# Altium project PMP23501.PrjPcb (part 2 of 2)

## Sheet DCDC_B.SchDoc: LM72880-Q1 EVM Schematic
size 431 x 279 mm; Date: Not shown in title block; ApprovedBy: Not shown in title block; CheckedBy: Not shown in title block; Author: Not shown in title block; CompanyName: Not shown in title block; DrawnBy: K Nielson; Engineer: E Lee; Organization: Not shown in title block; Address1: Not shown in title block; Address2: Not shown in title block; Address3: Not shown in title block; Address4: Not shown in title block; DocumentNumber: 5; Revision: Use project parameter SCH_Rev; SheetNumber: 5; SheetTotal: 7; PageSetup: Record=PageOptions¦CenterHorizontal=True¦CenterVertical=True¦PrintScale=1.00¦XCorrection=1.00¦YCorrection=1.00¦PrintKind=0¦BorderSize=5000000¦LeftOffset=0¦BottomOffset=0¦Orientation=2¦PaperLength=1000¦PaperWidth=1000¦Scale=100¦PaperSource=15¦PrintQuality=600¦MediaType=1¦DitherType=10¦PaperKind=Letter¦PrintScaleMode=1
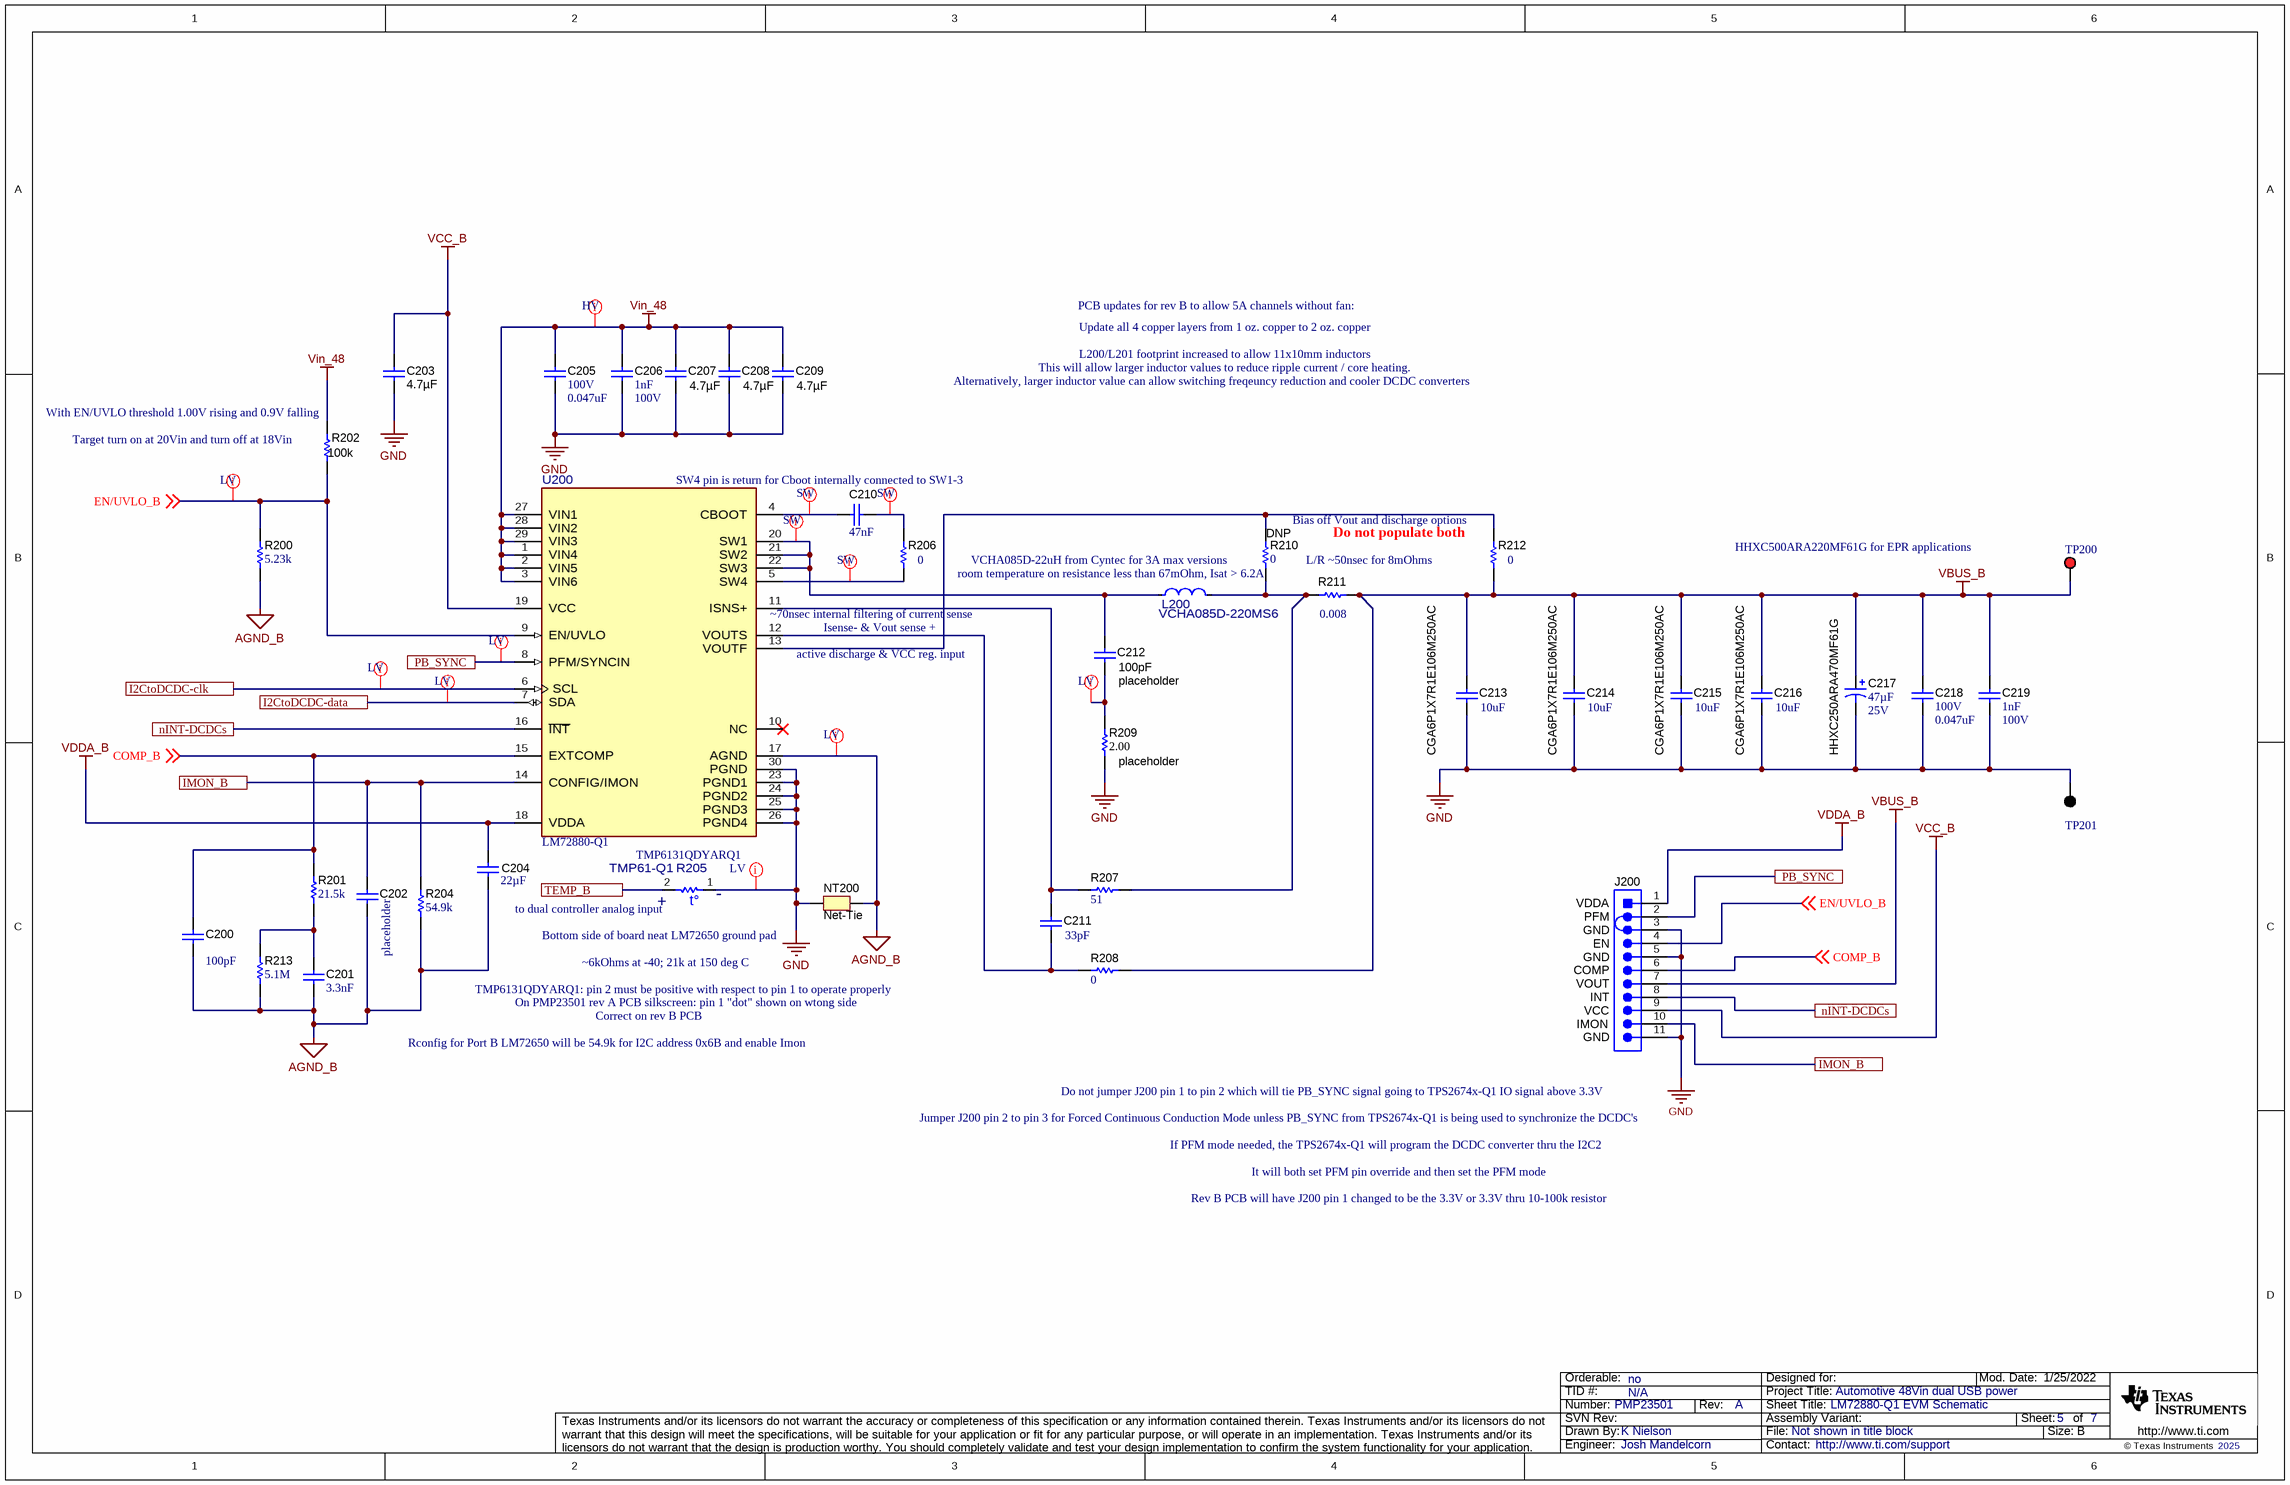
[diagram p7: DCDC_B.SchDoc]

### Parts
C200  ValueDisplayed: 100pF  [0603]  (hidden comment: GCM1885C2A101JA16D)
C201  Cap_F: 3.3nF  [0603]  (hidden comment: GCM188R72A332KA37D)
C202  ValueDisplayed: placeholder  [0603]  (hidden comment: GCM1885C2A100JA16D)
C203  Cap_F: 4.7µF  [0603]  (hidden comment: GRM188Z71A475ME15D)
C204  ValueDisplayed: 22µF  [0603]  (hidden comment: GRM188C80J226ME15D)
C205  VDC_V: 100V  ValueDisplayed: 0.047uF  [0603]  (hidden comment: CGA3E3X7S2A473K080AB)
C206  Cap_F: 1nF  VDC_V: 100V  [0603]  (hidden comment: CGA3E2X7R2A102K080AA)
C207  ValueDisplayed: 4.7µF  [1210_220]  (hidden comment: GCM32DC72A475KE02L)
C208  ValueDisplayed: 4.7µF  [1210_220]  (hidden comment: GCM32DC72A475KE02L)
C209  ValueDisplayed: 4.7µF  [1210_220]  (hidden comment: GCM32DC72A475KE02L)
C210  Cap_F: 47nF  [0603]  (hidden comment: CGA3E2X7R1H473K080AA)
C211  ValueDisplayed: 33pF  [0603]  (hidden comment: CGA3E2NP01H330J080AA)
C212  placeholder  ValueDisplayed: 100pF  [0603]
C213  CGA6P1X7R1E106M250AC  ValueDisplayed: 10uF  [1210_280]
C214  CGA6P1X7R1E106M250AC  ValueDisplayed: 10uF  [1210_280]
C215  CGA6P1X7R1E106M250AC  ValueDisplayed: 10uF  [1210_280]
C216  CGA6P1X7R1E106M250AC  ValueDisplayed: 10uF  [1210_280]
C217  HHXC250ARA470MF61G  ValueDisplayed: 47µF  VDC_V: 25V  [HXB_F61]
C218  VDC_V: 100V  ValueDisplayed: 0.047uF  [0603]  (hidden comment: CGA3E3X7S2A473K080AB)
C219  Cap_F: 1nF  VDC_V: 100V  [0603]  (hidden comment: CGA3E2X7R2A102K080AA)
J200  TSW-111-07-G-S  [TSW-111-07-G-S]  (value not drawn)
L200  VCHA085D-220MS6  [FP-VCHA075D-8R2MS6_SMD-MFG]
NT200  Net-Tie  [Net-Tie_10mil]  (net tie, no BOM)
R200  ValueDisplayed: 5.23k  [0603]  (hidden comment: CRCW06035K23FKEA)
R201  ValueDisplayed: 21.5k  [0603]  (hidden comment: CRCW060321K5FKEA)
R202  ValueDisplayed: 100k  [0603]  (hidden comment: CRCW0603100KFKEA)
R204  ValueDisplayed: 54.9k  [0603]  (hidden comment: CRCW060354K9FKEA)
R205  TMP61-Q1  PartNumber: TMP6131QDYARQ1  [DYA0002A-MFG]
R206  value 0  [0603]  (hidden comment: RC0603JR-070RL)
R207  ValueDisplayed: 51  [0603]  (hidden comment: CRCW060351R0JNEA)
R208  value 0  [0603]  (hidden comment: RC0603JR-070RL)
R209  placeholder  ValueDisplayed: 2.00  [0603]
R210  DNP  value 0  [0603]
R211  ValueDisplayed: 0.008  [KRL2012]  (hidden comment: KRL2012M-R008-F-T1)
R212  value 0  [0603]  (hidden comment: RC0603JR-070RL)
R213  ValueDisplayed: 5.1M  [0603]  (hidden comment: CRCW06035M10JNEA)
TP200  5000  [Keystone5000]  (value not drawn)
TP201  5001  [Keystone5001]  (value not drawn)
U200  LM72880-Q1  [RRX0029B-MFG]

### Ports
I2CtoDCDC-clk, I2CtoDCDC-data, IMON_B, nINT-DCDCs, PB_SYNC, TEMP_B

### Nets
AGND_B: C200.2 C201.2 C202.2 C204.1 NT200.2 R200.1 R204.1 R213.1 U200.17(AGND)
GND: C203.2 C205.2 C206.2 C207.2 C208.2 C209.2 C213.2 C214.2 C215.2 C216.2 C217.2(-) C218.2 C219.2 J200.3 J200.5 J200.11 NT200.1 R205.1(-) R209.2 TP201.1 U200.23(PGND1) U200.24(PGND2) U200.25(PGND3) U200.26(PGND4) U200.30(PGND)
VBUS_B: C213.1 C214.1 C215.1 C216.1 C217.1(+) C218.1 C219.1 J200.7 R208.2 R211.2 R212.2 TP200.1
VCC_B: C203.1 J200.9 U200.19(VCC)
VDDA_B: C204.2 J200.1 U200.18(VDDA)
Vin_48: C205.1 C206.1 C207.1 C208.1 C209.1 R202.2 U200.1(VIN4) U200.2(VIN5) U200.3(VIN6) U200.27(VIN1) U200.28(VIN2) U200.29(VIN3)
COMP_B: C200.1 J200.6 R201.2 U200.15(EXTCOMP) ; off-sheet COMP_B
EN/UVLO_B: J200.4 R200.2 R202.1 U200.9(EN/UVLO) ; off-sheet EN/UVLO_B
I2CtoDCDC-clk: U200.6(SCL) ; port I2CtoDCDC-clk
I2CtoDCDC-data: U200.7(SDA) ; port I2CtoDCDC-data
IMON_B: C202.1 J200.10 R204.2 U200.14(CONFIG/IMON) ; port IMON_B
nINT-DCDCs: J200.8 U200.16(~{INT}) ; port nINT-DCDCs
PB_SYNC: J200.2 U200.8(PFM/SYNCIN) ; port PB_SYNC
TEMP_B: R205.2(+) ; port TEMP_B
NetC201_1: C201.1 R201.1 R213.2
NetC210_1: C210.1 R206.1
NetC210_2: C210.2 U200.4(CBOOT)
NetC211_1: C211.1 R207.1 U200.11(ISNS+)
NetC211_2: C211.2 R208.1 U200.12(VOUTS)
NetC212_1: C212.1 L200.1 U200.20(SW1) U200.21(SW2) U200.22(SW3)
NetC212_2: C212.2 R209.1
NetL200_2: L200.2 R207.2 R210.1 R211.1
NetR206_2: R206.2 U200.5(SW4)
NetR210_2: R210.2 R212.1 U200.13(VOUTF)

Not connected (* = marked no-connect by the designer): U200 10(NC)*

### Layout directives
net class HV; Parameter 1: ClassName: Vin_48
net class SW; Parameter 1: ClassName: NetC210_1, NetC210_2, NetC212_1, NetR206_2
net class LV; Parameter 1: ClassName: AGND_B, EN/UVLO_B, GND, I2CtoDCDC-clk, I2CtoDCDC-data, NetC212_2, PB_SYNC

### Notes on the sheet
- PCB updates for rev B to allow 5A channels without fan:
- Update all 4 copper layers from 1 oz. copper to 2 oz. copper
- L200/L201 footprint increased to allow 11x10mm inductors
- This will allow larger inductor values to reduce ripple current / core heating.
- (near R202) With EN/UVLO threshold 1.00V rising and 0.9V falling
- Alternatively, larger inductor value can allow switching freqeuncy reduction and cooler DCDC converters
- (near R202) Target turn on at 20Vin and turn off at 18Vin
- SW4 pin is return for Cboot internally connected to SW1-3
- VCHA085D-22uH from Cyntec for 3A max versions
- (near R212) Bias off Vout and discharge options
- L/R ~50nsec for 8mOhms
- (near R212) Do not populate both
- HHXC500ARA220MF61G for EPR applications
- (near U200) ~70nsec internal filtering of current sense
- Isense- & Vout sense +
- (near R210) room temperature on resistance less than 67mOhm, Isat > 6.2A
- (near U200) active discharge & VCC reg. input
- (near R205) +
- (near R205) -
- (near J200) VDDA
- (near R205) to dual controller analog input
- Bottom side of board neat LM72650 ground pad
- ~6kOhms at -40; 21k at 150 deg C
- (near J200) COMP
- (near J200) GND
- (near J200) PFM
- (near J200) EN
- TMP6131QDYARQ1: pin 2 must be positive with respect to pin 1 to operate properly
- On PMP23501 rev A PCB silkscreen: pin 1 "dot" shown on wtong side
- Correct on rev B PCB
- (near J200) IMON
- (near J200) VOUT
- (near J200) VCC
- (near J200) INT
- Rconfig for Port B LM72650 will be 54.9k for I2C address 0x6B and enable Imon
- (near J200) Do not jumper J200 pin 1 to pin 2 which will tie PB_SYNC signal going to TPS2674x-Q1 IO signal above 3.3V
- Jumper J200 pin 2 to pin 3 for Forced Continuous Conduction Mode unless PB_SYNC from TPS2674x-Q1 is being used to synchronize the DCDC's
- If PFM mode needed, the TPS2674x-Q1 will program the DCDC converter thru the I2C2
- It will both set PFM pin override and then set the PFM mode
- Rev B PCB will have J200 pin 1 changed to be the 3.3V or 3.3V thru 10-100k resistor

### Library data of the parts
C200 = CMP-0007130-4: CAP, CERM, 100 pF, 100 V, +/- 5%, C0G/NP0, AEC-Q200 Grade 1, 0603; Manufacturer: MuRata; TaMin_C: -55°C; Polarized: N; SizeAreaWB_mm2: 4.68; Value1: Unknown; U/M: EA; TaMax_C: 125°C; SizeZ_mm: 1; SizeX_mm: 1.6; SizeY_mm: 0.8; Value2: 100V; SizeArea_mm2: 1.28; AEC Qualified: Y; AEC Category: Q200; Value: 100pF
C201 = CMP-0007148-4: CAP, CERM, 3300 pF, 100 V, +/- 10%, X7R, AEC-Q200 Grade 1, 0603; Manufacturer: MuRata; TaMin_C: -55°C; Polarized: N; SizeAreaWB_mm2: 4.68; Value1: Unknown; U/M: EA; Value: 3300pF; TaMax_C: 125°C; SizeZ_mm: 1; SizeX_mm: 1.6; SizeY_mm: 0.8; Value2: 100V; SizeArea_mm2: 1.28; AEC Qualified: Y; AEC Category: Q200
C202 = CMP-0084283-1: CAP, CERM, 10 pF, 100 V,+/- 5%, C0G/NP0, AEC-Q200 Grade 1, 0603; Manufacturer: MuRata; TaMax_C: 125°C; Cap_F: 10pF; Value2: 100V; SizeX_mm: 1.6; SizeY_mm: 0.8; SizeArea_mm2: 1.28; Polarized: N; AEC Category: Q200; SizeAreaWB_mm2: 4.68; AEC Qualified: Y; SizeZ_mm: 1; Value: 10pF; U/M: EA; TaMin_C: -55°C
C203 = CMP-0007498-4: CAP, CERM, 4.7 uF, 10 V, +/- 20%, X7R, 0603; Manufacturer: MuRata; Polarized: N; Value: 4.7uF; U/M: EA; Value1: Unknown; VDC_V: 10V; TaMin_C: -55°C; TaMax_C: 125°C; AEC Category: Q200; SizeArea_mm2: 1.28; SizeAreaWB_mm2: 4.68; SizeX_mm: 1.6; SizeY_mm: 0.8; SizeZ_mm: 1
C204 = CMP-0079996-1: CAP, CERM, 22 µF, 6.3 V,+/- 20%, X6S, 0603; Manufacturer: MuRata; Polarized: N; Value: 22uF; U/M: EA; VDC_V: 6.3V; TaMin_C: -55°C; TaMax_C: 105°C; AEC Category: Q200; SizeArea_mm2: 1.28; SizeAreaWB_mm2: 4.68; SizeX_mm: 1.6; SizeY_mm: 0.8; SizeZ_mm: 1
C205 C218 = CMP-0007101-4: CAP, CERM, 0.047 uF, 100 V, +/- 10%, X7S, AEC-Q200 Grade 1, 0603; Manufacturer: TDK; TaMin_C: -55°C; ESR_ohm: 89.796m; Polarized: N; SizeAreaWB_mm2: 4.68; Value1: 0.089796 ohm; U/M: EA; TaMax_C: 125°C; SizeZ_mm: 1; SizeX_mm: 1.6; SizeY_mm: 0.8; SizeArea_mm2: 1.28; AEC Qualified: Y; Cap_F: 47nF; IRMS_A: 567.484mA; AEC Category: Q200
C206 C219 = CMP-0007081-4: CAP, CERM, 1000 pF, 100 V, +/- 10%, X7R, AEC-Q200 Grade 1, 0603; Manufacturer: TDK; TaMin_C: -55°C; ESR_ohm: 1.9714; Polarized: N; SizeAreaWB_mm2: 4.68; Value1: 1.97137 ohm; U/M: EA; Value: 1000pF; TaMax_C: 125°C; SizeZ_mm: 1; SizeX_mm: 1.6; SizeY_mm: 0.8; SizeArea_mm2: 1.28; AEC Qualified: Y; IRMS_A: 305.705mA; AEC Category: Q200
C207-C209 = CMP-0082268-1: CAP, CERM, 4.7 µF, 100 V,+/- 10%, X7S, AEC-Q200 Grade 1, 1210; Manufacturer: MuRata; TaMin_C: -55°C; ESR_ohm: 1m; Polarized: N; SizeAreaWB_mm2: 14.7; Value1: 0.001 ohm; U/M: EA; Value: 4.7uF; TaMax_C: 125°C; SizeZ_mm: 2.2; SizeX_mm: 3.2; SizeY_mm: 2.5; Cap_Case: 1210; Value2: 100V; SizeArea_mm2: 8; AEC Qualified: Y; IRMS_A: 6A; AEC Grade: 1; AEC Category: Q200
C210 = CMP-0007079-4: CAP, CERM, 0.047 uF, 50 V, +/- 10%, X7R, AEC-Q200 Grade 1, 0603; Manufacturer: TDK; TaMin_C: -55°C; ESR_ohm: 49.007m; Polarized: N; SizeAreaWB_mm2: 4.68; Value1: 0.049007 ohm; U/M: EA; TaMax_C: 125°C; SizeZ_mm: 1; SizeX_mm: 1.6; SizeY_mm: 0.8; Value2: 50V; SizeArea_mm2: 1.28; AEC Qualified: Y; IRMS_A: 767.528mA; AEC Category: Q200
C211 = CMP-0007076-4: CAP, CERM, 33 pF, 50 V, +/- 5%, C0G/NP0, AEC-Q200 Grade 0, 0603; Manufacturer: TDK; TaMin_C: -55°C; Polarized: N; SizeAreaWB_mm2: 4.68; Value1: Unknown; U/M: EA; Value: 33pF; TaMax_C: 150°C; SizeZ_mm: 1; SizeX_mm: 1.6; SizeY_mm: 0.8; Value2: 50V; SizeArea_mm2: 1.28; AEC Qualified: Y; AEC Grade: 0; AEC Category: Q200
C212 = CMP-0007237-4: CAP, CERM, 100 pF, 100 V, +/- 5%, C0G/NP0, 0603; Manufacturer: MuRata; PartNumber: GRM1885C2A101JA01D; TaMin_C: -55°C; Polarized: N; SizeAreaWB_mm2: 4.68; Value1: Unknown; U/M: EA; Value: 100pF; TaMax_C: 125°C; SizeZ_mm: 1; SizeX_mm: 1.6; SizeY_mm: 0.8; Value2: 100V; SizeArea_mm2: 1.28; AEC Category: Q200
C213-C216 = CMP-0009155-2: CAP, CERM, 10 uF, 25 V, +/- 20%, X7R, AEC-Q200 Grade 1, 1210; Manufacturer: TDK; TaMin_C: -55°C; Polarized: N; SizeAreaWB_mm2: 14.7; Value1: Unknown; U/M: EA; Value: 10uF; TaMax_C: 125°C; SizeZ_mm: 2.8; SizeX_mm: 3.2; SizeY_mm: 2.5; Cap_Case: 1210; Value2: 25V; SizeArea_mm2: 8; AEC Qualified: Y; Cap_F: 10µF; AEC Grade: 1; AEC Category: Q200
C217 = CMP-0750159-1: CAP, AL, 47 µF, 25 V, +/- 20%, 0.05 ohm, AEC-Q200 Grade 1, SMD; Manufacturer: Chemi-Con; TaMin_C: -55°C; Cap_Case: 6.3x5.8mm; CompType: Capacitor; TaMax_C: 125°C; U/M: EA; Value: 47uF; AEC Grade: 1; AEC Category: Q200; AEC Qualified: Y; ESR_ohm: 50m
J200 = CMP-0075454-1: Header, 100mil, 11x1, Gold, TH; Manufacturer: Samtec; Pitch_mm: 2.54; Cert_VDE: N; Gender: Male; Cert_CSA: Y; Voltage_V: 550V; Green_REACh: Passed; Current_A: 6.3A; CT: False; Green_Lifecycle: Active; Row_Count: 1; CNHeader: True
L200 = CMP-0089036-1: Power Choke Coil; PartNumber: VCHA075D-8R2MS6; Manufacturer: Cyntec; DCR_ohm: 31.9m; AEC Grade: Grade 0; Ind_H: 8.2µH; Material: Metal dust; Isat: 9A; Irms: 5.6A; AEC Qualified: Yes; SizeZ_mm: 5.4mm
NT200 = CMP-0078142-6: Single point connection between nets.
R200 = CMP-0022510-4: RES, 5.23 k, 1%, 0.1 W, AEC-Q200 Grade 0, 0603; Manufacturer: Vishay-Dale; Power_W: 100mW; TempCo: 100 ppm/C; Value_Code: 5k23; Value: 5.23k; EIA_Code: E96; SizeX_mm: 1.6; SizeY_mm: 0.8; SizeZ_mm: 1; Value2: 0.1W; SizeArea_mm2: 1.28; AEC Qualified: Y; VDC_V: 75V; AEC Category: Q200; AEC Grade: 0
R201 = CMP-0022213-4: RES, 21.5 k, 1%, 0.1 W, AEC-Q200 Grade 0, 0603; Manufacturer: Vishay-Dale; Power_W: 100mW; TempCo: 100 ppm/C; Value_Code: 21k5; Value: 21.5k; EIA_Code: E96; SizeX_mm: 1.6; SizeY_mm: 0.8; SizeZ_mm: 1; Value2: 0.1W; SizeArea_mm2: 1.28; AEC Qualified: Y; VDC_V: 75V; AEC Category: Q200; AEC Grade: 0
R202 = CMP-0021990-4: RES, 100 k, 1%, 0.1 W, AEC-Q200 Grade 0, 0603; Manufacturer: Vishay-Dale; Power_W: 100mW; TempCo: 100 ppm/C; Value: 100k; EIA_Code: E96; SizeX_mm: 1.6; SizeY_mm: 0.8; SizeZ_mm: 1; Value2: 0.1W; SizeArea_mm2: 1.28; AEC Qualified: Y; VDC_V: 75V; AEC Category: Q200; AEC Grade: 0
R204 = CMP-0022494-4: RES, 54.9 k, 1%, 0.1 W, AEC-Q200 Grade 0, 0603; Manufacturer: Vishay-Dale; Power_W: 100mW; TempCo: 100 ppm/C; Value_Code: 54k9; Value: 54.9k; EIA_Code: E96; SizeX_mm: 1.6; SizeY_mm: 0.8; SizeZ_mm: 1; Value2: 0.1W; SizeArea_mm2: 1.28; AEC Qualified: Y; VDC_V: 75V; AEC Category: Q200; AEC Grade: 0
R205 = CMP-0123120-1: Automotive ±1% tolerance 10kΩ linear thermistor available in an 0402 package option 2-SOT-5X3 -40 to 150; Manufacturer: Texas Instruments; SizeZ_mm: 0.77mm; AEC Grade: Grade 0; AEC Qualified: Yes; Max Current: 400uA; TaMax_C: +150°C; TaMin_C: -40°C; TempCo: 6400ppm/°C; TJmax_C: +155°C; VDC_V: 5.5V
R206 R208 R212 = CMP-0025885-5: RES, 0, 5%, 0.1 W, 0603; Manufacturer: Yageo; SizeZ_mm: 1; AEC Qualified: N; VDC_V: 75V; Power_W: 100mW; TempCo: 200 ppm/C; Value_Code: 0000; EIA_Code: E24; SizeX_mm: 1.6; SizeY_mm: 0.8; Value2: 0.1W; SizeArea_mm2: 1.28; AEC Category: Q200; SizeAreaWB_mm2: 4.68
R207 = CMP-0025825-4: RES, 51, 5%, 0.1 W, AEC-Q200 Grade 0, 0603; Manufacturer: Vishay-Dale; Power_W: 100mW; TempCo: 200 ppm/C; Value_Code: 51R0; Value: 51; EIA_Code: E24; SizeX_mm: 1.6; SizeY_mm: 0.8; SizeZ_mm: 1; Value2: 0.1W; SizeArea_mm2: 1.28; AEC Qualified: Y; VDC_V: 75V; AEC Category: Q200; AEC Grade: 0
R209 = CMP-0022302-4: RES, 2.00, 1%, 0.1 W, AEC-Q200 Grade 0, 0603; Manufacturer: Vishay-Dale; PartNumber: CRCW06032R00FKEA; Power_W: 100mW; TempCo: 100 ppm/C; Value_Code: 2R00; Value: 2.00; EIA_Code: E96; Res_ohm: 2; SizeX_mm: 1.6; SizeY_mm: 0.8; SizeZ_mm: 1; Value2: 0.1W; SizeArea_mm2: 1.28; AEC Qualified: Y; VDC_V: 75V; AEC Category: Q200; AEC Grade: 0
R210 = CMP-0025885-5: RES, 0, 5%, 0.1 W, 0603; Manufacturer: Yageo; PartNumber: RC0603JR-070RL; SizeZ_mm: 1; AEC Qualified: N; VDC_V: 75V; Power_W: 100mW; TempCo: 200 ppm/C; Value_Code: 0000; EIA_Code: E24; SizeX_mm: 1.6; SizeY_mm: 0.8; Value2: 0.1W; SizeArea_mm2: 1.28; AEC Category: Q200; SizeAreaWB_mm2: 4.68
R211 = CMP-0015103-2: RES, 0.008, 1%, 1 W, AEC-Q200 Grade 0, 0508; Manufacturer: Susumu Co Ltd; Value: 0.008; Res_ohm: 8m; AEC Grade: 0; Power_W: 1W; TempCo: 25 ppm/C; AEC Qualified: Y; Value_Code: 8L000; U/M: EA; EIA_Code: E96; AEC Category: Q200
R213 = CMP-0025832-4: RES, 5.1 M, 5%, 0.1 W, AEC-Q200 Grade 0, 0603; Manufacturer: Vishay-Dale; Power_W: 100mW; TempCo: 200 ppm/C; Value_Code: 5M10; Value: 5.1Meg; EIA_Code: E24; SizeX_mm: 1.6; SizeY_mm: 0.8; SizeZ_mm: 1; Value2: 0.1W; SizeArea_mm2: 1.28; AEC Qualified: Y; VDC_V: 75V; AEC Category: Q200; AEC Grade: 0
TP200 = CMP-0055137-2: Test Point, Miniature, Red, TH; Manufacturer: Keystone Electronics; Green_REACh: Passed; CT: TRUE; ContactFinish: Silver; CNHeader: FALSE; Green_Lifecycle: Active
TP201 = CMP-0055138-2: Test Point, Miniature, Black, TH; Manufacturer: Keystone Electronics; ContactFinish: Silver; Green_Lifecycle: Active; Green_REACh: Passed; CT: TRUE; CNHeader: FALSE
U200 = CMP-0123475-2: Manufacturer: Texas Instruments; SizeZ_mm: 1mm; AEC Qualified: No; Standoff Height: 0mm; AEC Category: Q200; CompType: IC

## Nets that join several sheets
3.3V: EPR_Controller_Dual (9 pins), DCDC_A (R30.2 R31.2 R32.2), USB-Cconecctors&protection (C140.1 C240.1 U140.10 U240.10)
GND: InputPower&Protection (9 pins), EPR_Controller_Dual (20 pins), DCDC_A (26 pins), USB-Cconecctors&protection (40 pins), DCDC_B (25 pins)
VBUS_A: EPR_Controller_Dual (R10.1), DCDC_A (12 pins), USB-Cconecctors&protection (6 pins)
VBUS_B: EPR_Controller_Dual (R14.1), USB-Cconecctors&protection (6 pins), DCDC_B (12 pins)
VDDA_A: EPR_Controller_Dual (C12.1 U10.4), DCDC_A (C104.2 J100.1 U100.18)
Vin_48: InputPower&Protection (C9.1 L2.2 TP3.1), EPR_Controller_Dual (Q10.3 R23.2 R25.1), DCDC_A (12 pins), DCDC_B (12 pins)
CC1_A: EPR_Controller_Dual (C17.2 U10.3), USB-Cconecctors&protection (D130.2 R135.1 U140.12)
CC1_B: EPR_Controller_Dual (C18.1 U10.6), USB-Cconecctors&protection (D230.2 R235.1 U240.12)
CC2_A: EPR_Controller_Dual (C15.2 U10.2), USB-Cconecctors&protection (D130.1 R136.1 U140.11)
CC2_B: EPR_Controller_Dual (C16.1 U10.7), USB-Cconecctors&protection (D230.1 R236.1 U240.11)
D+_A: EPR_Controller_Dual (U10.29), USB-Cconecctors&protection (D131.2 R137.1 U140.15)
D+_B: EPR_Controller_Dual (U10.8), USB-Cconecctors&protection (D231.2 R237.1 U240.15)
D-_A: EPR_Controller_Dual (U10.28), USB-Cconecctors&protection (D131.1 R138.1 U140.14)
D-_B: EPR_Controller_Dual (U10.10), USB-Cconecctors&protection (D231.1 R238.1 U240.14)
I2CtoDCDC-clk: EPR_Controller_Dual (U10.22), DCDC_A (J30.9 R31.1 U100.6), DCDC_B (U200.6)
I2CtoDCDC-data: EPR_Controller_Dual (U10.23), DCDC_A (J30.10 R30.1 U100.7), DCDC_B (U200.7)
IMON_A: EPR_Controller_Dual (U10.31), DCDC_A (C102.1 J100.10 R104.2 U100.14)
IMON_B: EPR_Controller_Dual (U10.1), DCDC_B (C202.1 J200.10 R204.2 U200.14)
nINT-DCDCs: EPR_Controller_Dual (R12.2 R13.2), DCDC_A (J100.8 U100.16), DCDC_B (J200.8 U200.16)
PA_SYNC: EPR_Controller_Dual (U10.21), DCDC_A (J100.2 U100.8)
PB_SYNC: EPR_Controller_Dual (U10.16), DCDC_B (J200.2 U200.8)
TEMP_A: EPR_Controller_Dual (C13.1 R16.1 U10.11), DCDC_A (R105.2)
TEMP_B: EPR_Controller_Dual (C14.1 R21.1 U10.12), DCDC_B (R205.2)

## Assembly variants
for purposes of layout: not fitted FID1 FID2 FID3 NT100 NT200
PMP23501_20Vout60Weach: not fitted C102 C112 C140 C141 C202 C212 C240 C241 FID1 FID2 FID3 R20 R23 R30 R31 R32 R109 R110 R209 R210 U140 U240
EPR - up to 48Vout: not fitted C102 C112 C202 C212 D130 D131 D230 D231 R109 R110 R135 R136 R137 R138 R209 R210 R235 R236 R237 R238; alternate parts U100 -> CMP-0123532-1, U200 -> CMP-0123532-1, L100 -> CMP-0060087-2, L200 -> CMP-0060087-2, C113 -> CMP-0092450-1, C114 -> CMP-0092450-1, C115 -> CMP-0092450-1, C116 -> CMP-0092450-1, C213 -> CMP-0092450-1, C214 -> CMP-0092450-1, C215 -> CMP-0092450-1, C216 -> CMP-0092450-1, C117 -> CMP-0012601-3, C217 -> CMP-0012601-3, R101 -> CMP-0022043-4, R201 -> CMP-0022043-4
